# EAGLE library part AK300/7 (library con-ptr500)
CONNECTOR
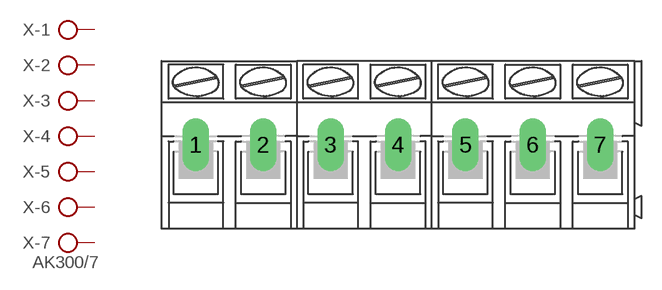
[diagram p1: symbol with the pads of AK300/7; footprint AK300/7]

Designator prefix X; gates -1=KL -2=KL -3=KL -4=KL -5=KL -6=KL -7=KLV

## AK300/7 (OC_FARNELL: unknown; OC_NEWARK: unknown)  [AK300/7]
1  -1:KL  pas
2  -2:KL  pas
3  -3:KL  pas
4  -4:KL  pas
5  -5:KL  pas
6  -6:KL  pas
7  -7:KL  pas

## Footprint AK300/7 (pad centres in mm)
CONNECTOR
drill 1.321 long: 1 -15.011,0; 2 -10.008,0; 3 -5.004,0; 4 0,0; 5 5.004,0; 6 10.008,0; 7 15.011,0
